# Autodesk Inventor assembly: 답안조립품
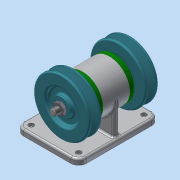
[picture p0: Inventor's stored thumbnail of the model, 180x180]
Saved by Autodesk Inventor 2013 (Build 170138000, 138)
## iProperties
Created: 2019-09
Part Number: 답안조립품
Document SubType Name: Assembly
Designer: Administrator
Author: Administrator
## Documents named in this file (10)
- C:\Users\Administrator\Desktop\490904V1051\답안조립품.iam
- C:\Users\Administrator\Desktop\490904V1051\본체.ipt
- C:\Users\Administrator\Desktop\490904V1051\V-벨트풀리.ipt
- C:\Users\Administrator\Desktop\490904V1051\너트 M10x1.ipt
- C:\Users\Administrator\Desktop\490904V1051\베어링 6004.ipt
- C:\Users\Administrator\Desktop\490904V1051\볼트 M4.ipt
- C:\Users\Administrator\Desktop\490904V1051\오일 실 17 30 5.ipt
- C:\Users\Administrator\Desktop\490904V1051\축.ipt
- C:\Users\Administrator\Desktop\490904V1051\커버.ipt
- C:\Users\Administrator\Desktop\490904V1051\키 5 x 5 x 12.ipt
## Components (2 placed, 1 different names)
1. V-벨트풀리:1
2. V-벨트풀리:2
